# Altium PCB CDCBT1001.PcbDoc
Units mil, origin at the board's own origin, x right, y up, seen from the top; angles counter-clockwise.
Board outline 2000 x 1000 mil, 4 copper layers (Top Layer, GND2, GND3, Bottom Layer), stack 61.4 mil thick; 14 components, 7 nets, 34 pads, 29 vias.
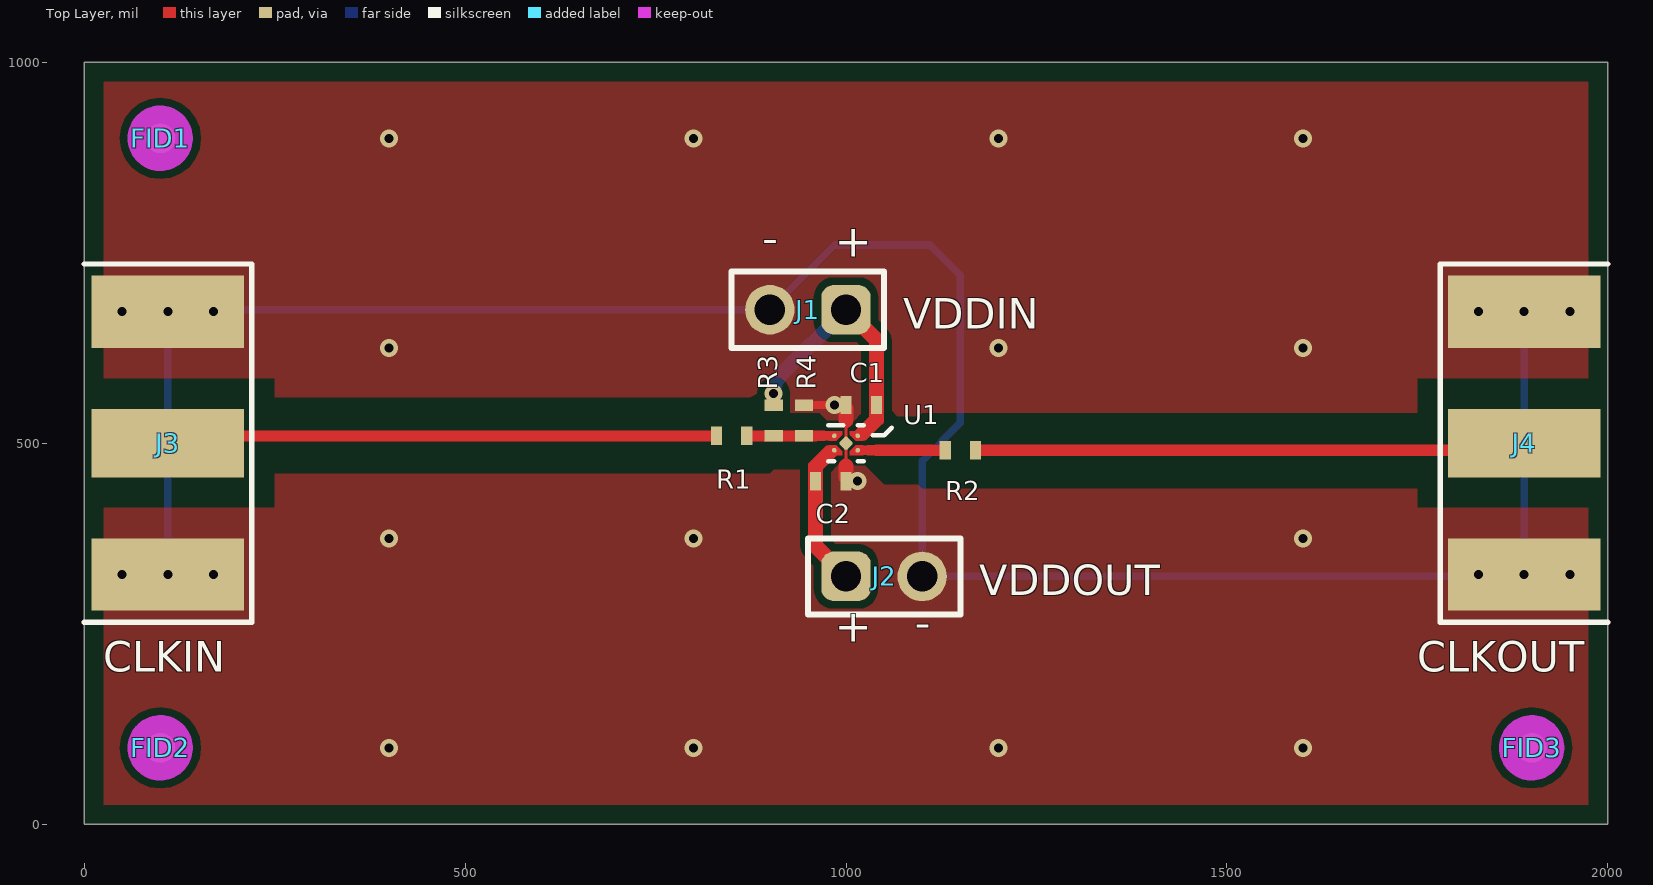
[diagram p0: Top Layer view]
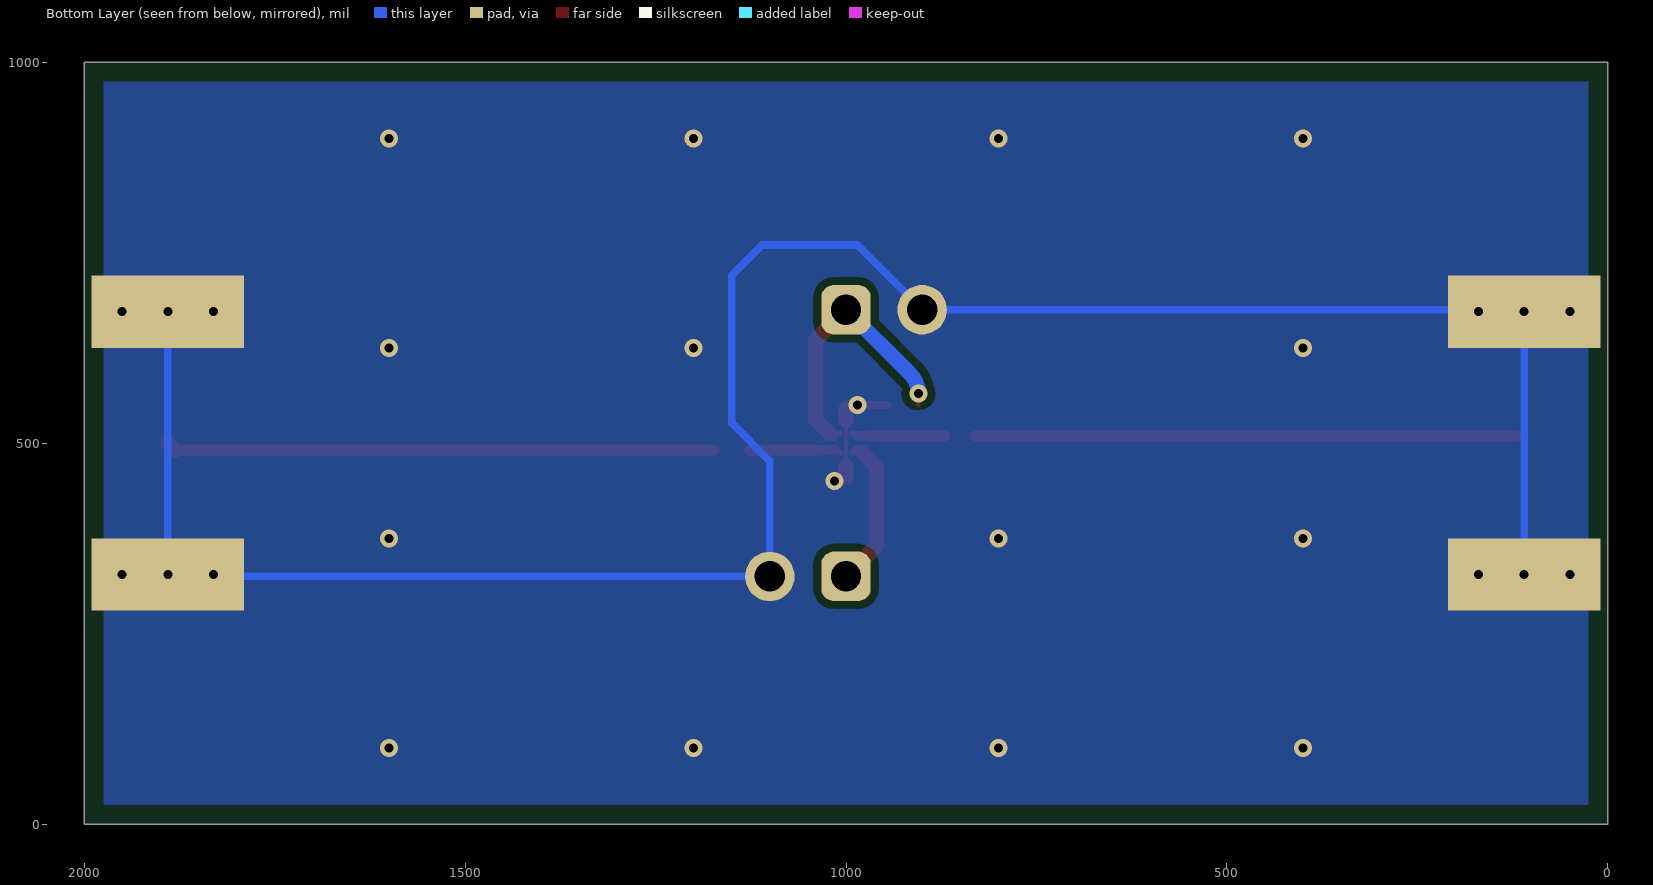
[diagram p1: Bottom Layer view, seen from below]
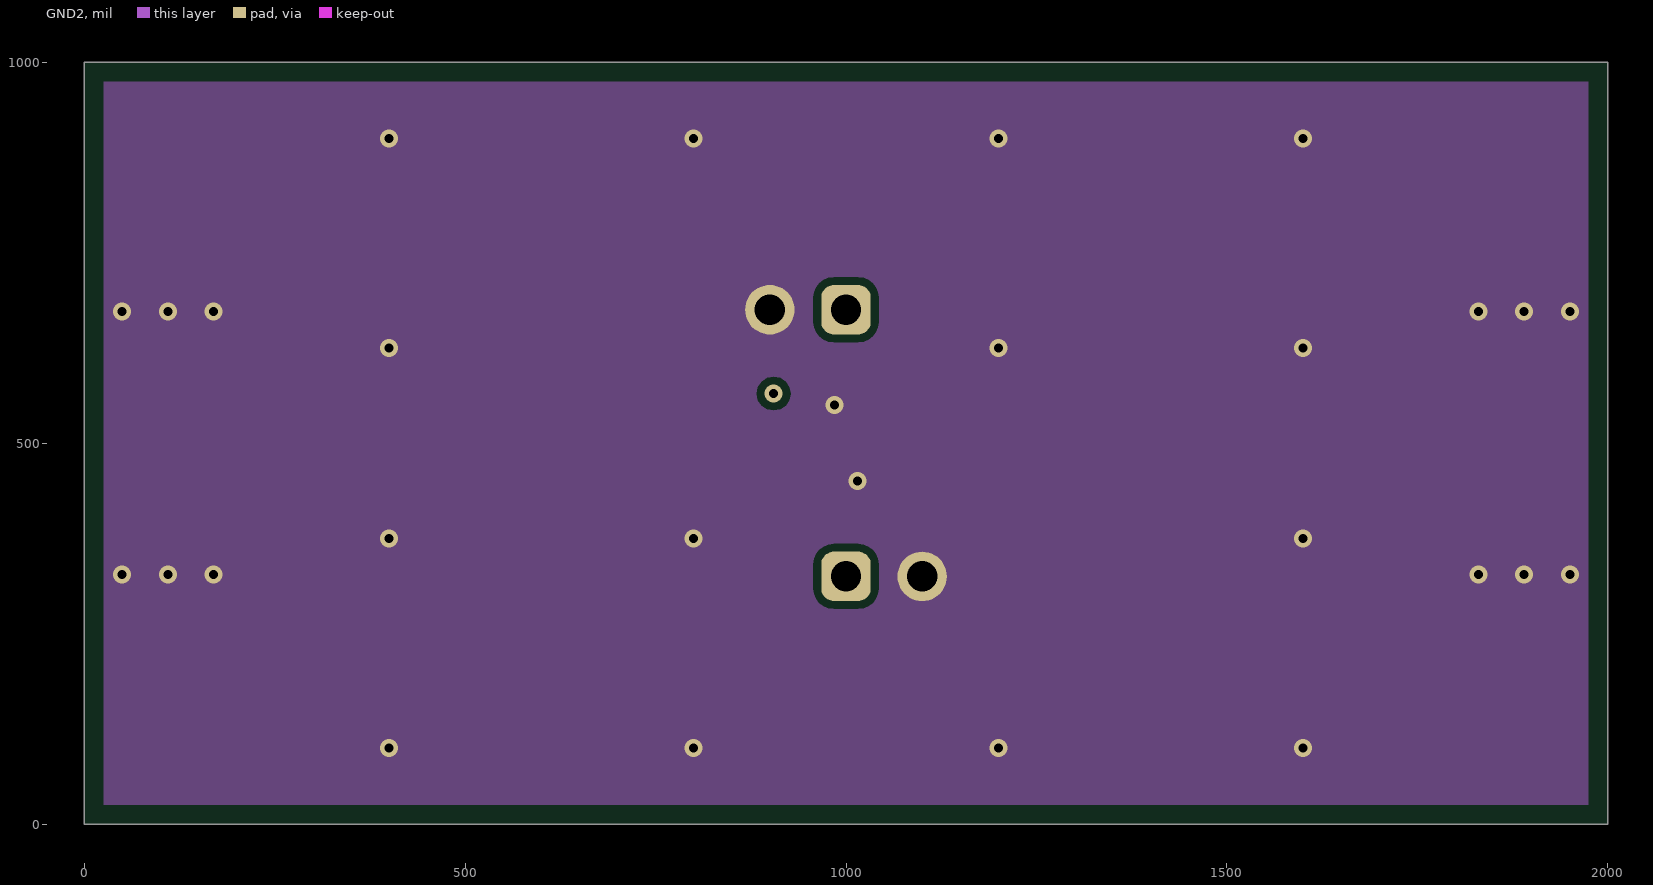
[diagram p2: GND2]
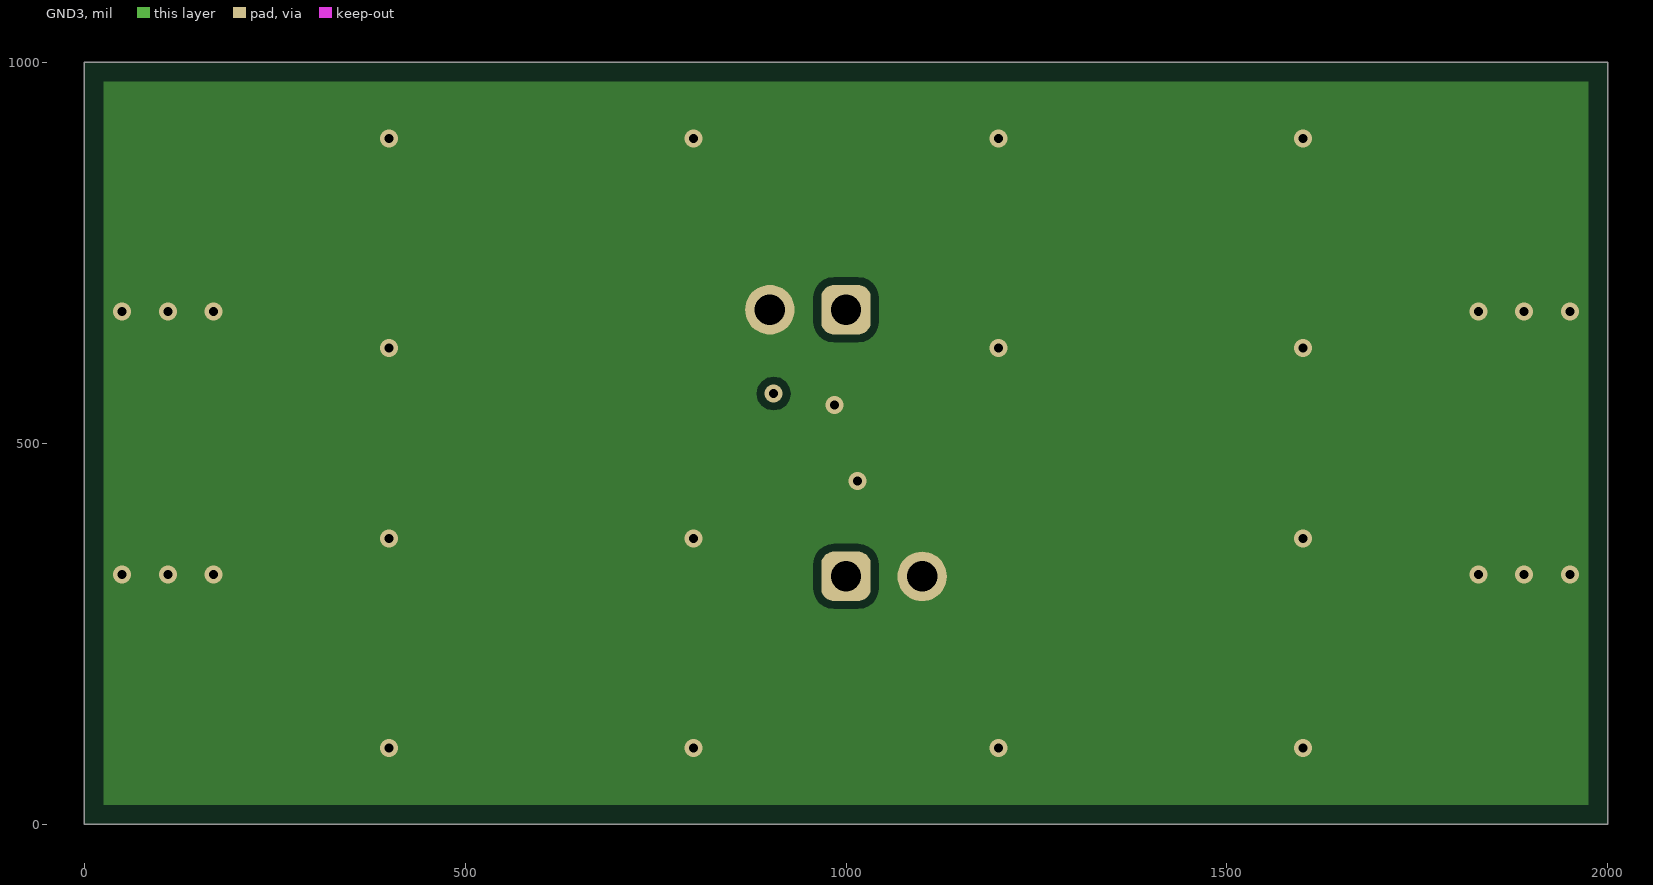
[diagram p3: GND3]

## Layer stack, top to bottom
Top Solder: solder mask 0.4, Solder Resist, Dk 3.5
Top Layer: signal copper 1.2
Dielectric 1: prepreg 8, FR-4, Dk 4.2
GND2: signal copper 1.4
Dielectric 2: core 40, FR-4, Dk 4.2
GND3: signal copper 1.4
Dielectric 3: prepreg 8, FR-4, Dk 4.2
Bottom Layer: signal copper 1.4
Bottom Solder: solder mask 0.4, Solder Resist, Dk 3.5

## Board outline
0,0 0,1000 2000,1000 2000,0

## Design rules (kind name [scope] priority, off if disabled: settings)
AcuteAngle [All] p1: minimum=4.50000000000000E+0001 checktracksonly=FALSE
AssemblyTestPointUsage [All] p1: valid=2
BoardOutlineClearance BoardOutlineClearance_MountingHoles [OnCopper and InComponentClass('Mounting Holes')] p1: gap=39.37 ignorepadtopadclearanceinfootprint=FALSE
BoardOutlineClearance BoardOutlineClearance_Poly [OnCopper and IsPoly] p2: gap=25 ignorepadtopadclearanceinfootprint=FALSE
BoardOutlineClearance [OnCopper and Not InComponentClass('Logo') and not InComponentClass('FiducialMark') and not InRegion(1000,500,4000,800) and not InPoly and not InComponent('J3') and not InComponent('J4')] p3: gap=40 ignorepadtopadclearanceinfootprint=FALSE except(25: Via-OutlineEdge Poly-OutlineEdge)
Clearance Clearance_Keepouts [((IsTrack Or IsArc) And Not InPoly) And IsFree and IsKeepOut vs ((IsTrack Or IsArc) And Not InPoly) And IsFree and IsKeepOut] p1: gap=0 ignorepadtopadclearanceinfootprint=FALSE
Clearance Clearance_Poly [InPolygon] p2: gap=10 ignorepadtopadclearanceinfootprint=TRUE
Clearance Clearance_FiducialMark [IsKeepOut and InComponentClass('FiducialMark') vs IsPad and InComponentClass('FiducialMark')] p3: gap=0 ignorepadtopadclearanceinfootprint=FALSE
Clearance [All and not InComponent('U1') and not InNet('NetR2_1') and not InNet('NetR1_2') and not InNet('NetC1_1') and not InNet('NetC2_1')and not InNet('GND')] p4: gap=7.87 ignorepadtopadclearanceinfootprint=TRUE
ComponentClearance ComponentClearance_MountingHoles_FiducialMarks [InComponentClass('Mounting Holes') vs InComponentClass('FiducialMark')] p1: gap=50 collisioncheckmode=3 verticalgap=10 showdistances=FALSE
ComponentClearance ComponentClearance_Shunt [InComponentClass('Header') vs InComponentClass('Shunt')] p2: gap=0 collisioncheckmode=3 verticalgap=0 showdistances=FALSE
ComponentClearance ComponentClearance_Logo [InComponentClass('Logo')] p3: gap=30 collisioncheckmode=3 verticalgap=10 showdistances=FALSE
ComponentClearance ComponentClearance_ScrewToNut [(HasFootprint('NY PMS 440 0025 PH')) vs (HasFootprint('Keystone_1902C'))] p4: gap=5 collisioncheckmode=3 verticalgap=10 showdistances=FALSE
ComponentClearance ComponentClearance_MountingHoles [InComponentClass('Mounting Holes')] p5: gap=100 collisioncheckmode=3 verticalgap=100000 showdistances=FALSE
ComponentClearance ComponentClearance_SmallPassives [HasFootprint('0201*') or HasFootprint('0402*') or HasFootprint('0508') or HasFootprint('0603*') or HasFootprint('0612') or HasFootprint('0805*') or HasFootprint('0815*') or HasFootprint('0830*') or HasFootprint('1206*') or HasFootprint('1210*') or HasFootprint('1808*') or HasFootprint('1812*') or HasFootprint('1825*') or HasFootprint('2010*') or HasFootprint('2220*') or HasFootprint('2225*') or HasFootprint('2512*') or HasFootprint('2728*') or HasFootprint('3518*') vs HasFootprint('0201*') or HasFootprint('0402*') or HasFootprint('0508') or HasFootprint('0603*') or HasFootprint('0612') or HasFootprint('0805*') or HasFootprint('0815*') or HasFootprint('0830*') or HasFootprint('1206*') or HasFootprint('1210*') or HasFootprint('1808*') or HasFootprint('1812*') or HasFootprint('1825*') or HasFootprint('2010*') or HasFootprint('2220*') or HasFootprint('2225*') or HasFootprint('2512*') or HasFootprint('2728*') or HasFootprint('3518*')] p6: gap=14.96 collisioncheckmode=3 verticalgap=10 showdistances=FALSE
ComponentClearance ComponentClearance_THtoSMT [IsThruComponent vs IsSMTComponent] p7: gap=30 collisioncheckmode=3 verticalgap=30 showdistances=FALSE
ComponentClearance ComponentClearance_THtoTH [IsThruComponent vs IsThruComponent] p8: gap=20 collisioncheckmode=3 verticalgap=30 showdistances=FALSE
ComponentClearance [All] p9: gap=20 collisioncheckmode=3 verticalgap=10 showdistances=FALSE
DiffPairsRouting [All] p1: maxlimit=100 minlimit=10 mostfreqgap=10 toplayer_minwidth=15 toplayer_maxwidth=15 toplayer_prefwidth=15 midlayer1_minwidth=15 midlayer1_maxwidth=15 midlayer1_prefwidth=15 midlayer2_minwidth=15 midlayer2_maxwidth=15 midlayer2_prefwidth=15 bottomlayer_minwidth=15 bottomlayer_maxwidth=15 bottomlayer_prefwidth=15 maxuncoupledlength=1000
FabricationTestPointUsage TestPointUsage [All] p1: valid=2 allowmultiple=FALSE
FabricationTestpoint Testpoint [All] p1: side=3 testpointundercomponent=TRUE minsize=40 maxsize=100 preferedsize=60 minholesize=0 maxholesize=40 preferedholesize=32 testpointgrid=1 allowsidetop=TRUE allowsidebottom=TRUE usegrid=TRUE gridtolerance=0.01
FanoutControl Fanout_LCC [IsLCC] p1: bgadir=Out bgaviamode=Centered fanoutstyle=Auto fanoutdirection=Alternating viagrid=1 // Fanout_LCC (Default Rule)
FanoutControl Fanout_BGA [IsBGA] p2: bgadir=Out bgaviamode=Centered fanoutstyle=Auto fanoutdirection=Alternating viagrid=1 // Fanout_BGA (Default Rule)
FanoutControl Fanout_Default [All] p4: bgadir=Out bgaviamode=Centered fanoutstyle=Auto fanoutdirection=Alternating viagrid=1 // Fanout_Default (Default Rule)
FanoutControl Fanout_Small [(CompPinCount < 5)] p5: bgadir=Out bgaviamode=Centered fanoutstyle=Auto fanoutdirection=OutThenIn viagrid=1 // Fanout_Small (Default Rule)
HoleSize [All] p1: absolutevalues=TRUE maxlimit=251 minlimit=3 maxpercent=80.000 minpercent=20.000
MinimumAnnularRing MinimumAnnularRing_ThermalPadVias [IsVia and InAnyComponent] p1: minimumring=3
MinimumAnnularRing [All] p2: minimumring=3.5
MinimumSolderMaskSliver MinimumSolderMaskSliver_Logo [InComponentClass('Logo') vs InComponentClass('Logo')] p1: minsoldermaskwidth=0.7
MinimumSolderMaskSliver [All] p2: minsoldermaskwidth=3.94
PlaneConnect [All] p1: planeconnectstyle=Relief reliefexpansion=10 reliefentries=4 reliefconductorwidth=10 reliefairgap=10
PolygonConnect [All] p1: connectstyle=Direct reliefconductorwidth=10 reliefentries=4 polygonreliefangle="90 Angle" airgapwidth=10
RoutingVias ThermalPadVias [IsVia and InAnyComponent] p1: holewidth=7.87 width=19.68 viastyle="Through Hole" minholewidth=3 minwidth=10 maxholewidth=12.99 maxwidth=23.62
RoutingVias [All] p2: holewidth=16 width=34 viastyle="Through Hole" minholewidth=3 minwidth=10 maxholewidth=40 maxwidth=65
SilkToBoardRegionClearance [Not ((IsComment or IsDesignator) And (Hide <> 'False')) and not InRegion(1000,500,4000,800)] p1:
SilkToSilkClearance SilkToSilkClearance_Pb-FreeLogo [(HasFootprint('Pb-Free_Overlay_Medium') OR HasFootprint('Pb-Free_Overlay_Small')) vs (HasFootprint('Pb-Free_Overlay_Medium') OR HasFootprint('Pb-Free_Overlay_Small'))] p1: silktosilkclearance=0
SilkToSilkClearance [All] p2: silktosilkclearance=3.94
SilkToSolderMaskClearance SilkToComponentPadClearance [(IsPad or IsFill or IsRegion) and InAnycomponent] p1: minsilkscreentomaskgap=5 clearancetoexposedcopper=TRUE
SilkToSolderMaskClearance "Silk to Solder Mask Opening" [All] p2: minsilkscreentomaskgap=3.94 clearancetoexposedcopper=FALSE
SolderMaskExpansion [All] p1: expansion=1.97
UnRoutedNet [All] p1: checkbadconnections=TRUE
Width [All] p1: maxlimit=100 minlimit=3.5 preferedwidth=10 checkconnectedcopper=TRUE
14 further rules are at their usual default settings.

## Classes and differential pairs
component class Header: J1 J2
component class FiducialMark: FID1 FID2 FID3

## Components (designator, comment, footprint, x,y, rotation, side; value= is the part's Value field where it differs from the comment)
C1 "885012205037" 0402S 1020,550 r180 top value=0.1µF
C2 "885012205037" 0402S 980,450 r0 top value=0.1µF
FID1 "Fiducial" Fiducial10-20 100,900 r0 top
FID2 "Fiducial" Fiducial10-20 100,100 r0 top
FID3 "Fiducial" Fiducial10-20 1900,100 r0 top
J1 "VDDIN" TSW-102-07-G-S 950,675 r180 top
J2 "VDDOUT" TSW-102-07-G-S 1050,325 r0 top
J3 "CLKIN" Emerson_142-0701-851 0,500 r90 top
J4 "CLKOUT" Emerson_142-0701-851 2000,500 r270 top
R1 "CRCW040215R0FKED" 0402S 850,509.45 r0 top value=15.0
R2 "CRCW040215R0FKED" 0402S 1150,490.55 r0 top value=15.0
R3 "CRCW0402100RFKED" 0402S 905,529.45 r90 top value=100
R4 "CRCW0402100RFKED" 0402S 945,529.45 r270 top value=100
U1 "CDCBT1001DPWR" DPW0005A-MFG 1000,500 r0 top

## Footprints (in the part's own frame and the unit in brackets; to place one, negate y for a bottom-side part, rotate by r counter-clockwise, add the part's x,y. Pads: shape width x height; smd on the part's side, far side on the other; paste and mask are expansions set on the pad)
0402S [mil] "Based on C0402S footprint from PADS legacy"
  rect 15x24 smd: 1(-20,0) 2(20,0)
  body extent -22,-12 22,12, height 24
DPW0005A-MFG [mm]
  round 0.152 smd paste-1000 mask-1000: 1(-0.39,0.24) 2(-0.39,-0.24) 4(0.39,-0.24) 5(0.39,0.24)
  rrect29% 0.35x0.35 smd rot 135 paste-1000 mask-1000: 3(0,0)
  Top Layer region: 0.65,-0.3 0.637,-0.35 0.6,-0.387 0.55,-0.4 0.55,-0.4 0.13,-0.4 0.13,-0.27 0.32,-0.08 0.55,-0.08 0.6,-0.093 0.637,-0.13 0.65,-0.18 0.65,-0.18
  Top Layer region: -0.65,-0.3 -0.637,-0.35 -0.6,-0.387 -0.55,-0.4 -0.55,-0.4 -0.13,-0.4 -0.13,-0.27 -0.32,-0.08 -0.55,-0.08 -0.6,-0.093 -0.637,-0.13 -0.65,-0.18 -0.65,-0.18
  Top Layer region: 0.65,0.3 0.637,0.35 0.6,0.387 0.55,0.4 0.55,0.4 0.13,0.4 0.13,0.27 0.32,0.08 0.55,0.08 0.6,0.093 0.637,0.13 0.65,0.18 0.65,0.18
  Top Layer region: -0.65,0.3 -0.637,0.35 -0.6,0.387 -0.55,0.4 -0.55,0.4 -0.13,0.4 -0.13,0.27 -0.32,0.08 -0.55,0.08 -0.6,0.093 -0.637,0.13 -0.65,0.18 -0.65,0.18
  silkscreen extent -0.6,-0.6 0.6,0.6, body extent -0.75,-0.53 0.75,0.53, height 0.25
Emerson_142-0701-851 [mil] "Cinch Connectivity"
  rect 90x200 smd: 1(0,-110)
  rect 95x200 smd: 2(-172.5,-110) 3(172.5,-110)
  rect 95x200 smd far side: 4(172.5,-110) 5(-172.5,-110)
  silkscreen extent -235,-220 235,0, body extent -190,-195 190,387, height 155
Fiducial10-20 [mm]
  round 1 smd mask+0.5: 1(0,0)
  Top Layer keep-out circle w1.178: c0,0 r0.5
TSW-102-07-G-S [mm] "Samtec 100mil, 1x2, 230 mil above insulator"
  rrect50% 1.65x1.65 hole 1.016: 1(-1.27,0)
  round 1.65 hole 1.016: 2(1.27,0)
  silkscreen extent -2.54,-1.27 2.54,1.27, body extent -2.54,-1.27 2.54,1.27, height 8.38

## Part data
C1 C2: library part CMP-0006228-2, "CAP, CERM, 0.1 uF, 16 V, +/- 10%, X7R, 0402", Cap_Case=0402, Manufacturer="Wurth Elektronik", Supplier Part Number 1=732-7532-1-ND, TempCo=X7R, Tolerance_%=10%, Value1=Unknown, Value2=16V, ValueDisplayed=0.1µF
FID1 FID2 FID3: library part CMP-0077181-1, "Fiducial mark.  There is nothing to buy or mount.", Manufacturer=N/A
J1 J2: library part CMP-0075405-3, "Header, 100mil, 2x1, Gold, TH", Color=Black, Current_A=6.3A, Manufacturer=Samtec, PartNumber=TSW-102-07-G-S, Supplier Part Number 1=SAM1029-02-ND, Voltage_V=550V
J3 J4: library part CMP-0055822-3, "Connector, End launch SMA, 50 ohm, SMT", Manufacturer="Cinch Connectivity", PartNumber=142-0701-851, Supplier Part Number 1=J658-ND
R1 R2: library part CMP-0026030-3, "RES, 15.0, 1%, 0.063 W, AEC-Q200 Grade 0, 0402", Manufacturer=Vishay-Dale, Power_W=63mW, Supplier Part Number 1=541-15.0LCT-ND, TempCo="100 ppm/C", Tolerance_%=1%, Value2=0.063W, Value_Code=15R0, ValueDisplayed=15.0
R3 R4: library part CMP-0025951-3, "RES, 100, 1%, 0.063 W, AEC-Q200 Grade 0, 0402", Manufacturer=Vishay-Dale, Power_W=63mW, Supplier Part Number 1=541-100LCT-ND, TempCo="100 ppm/C", Tolerance_%=1%, Value2=0.063W, Value_Code=100R, ValueDisplayed=100
U1: library part CMP-0094493-1, "1.2 to 1.8-V Clock Buffer And Level Translator", Frequency_Fixed=24MHz, Manufacturer="Texas Instruments", Operating Temperature Range="-40°C to +85°C"

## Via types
v1: diameter 23.62, hole 11.81, Top Layer to Bottom Layer, tented both sides, 29 vias

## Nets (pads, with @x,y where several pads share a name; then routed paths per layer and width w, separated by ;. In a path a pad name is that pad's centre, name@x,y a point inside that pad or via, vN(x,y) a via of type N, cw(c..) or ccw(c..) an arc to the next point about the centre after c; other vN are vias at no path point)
GND: C1.2 C2.2 J1.2 J2.2 J3.2 J3.3 J3.4 J3.5 J4.2 J4.3 J4.4 J4.5 R4.1 U1.3 | length 3174.7
  Top Layer w4: C2.2 U1.3 C1.2
  Top Layer w10: R4.1 cw(c946.33,548.12) 946.33,550 v1(985,550) C1.2
  Top Layer w20: C2.2@1000,455 1000,470 ; 1000,530 C1.2@1000,545
  Bottom Layer w10: v1(110,327.5) v1(110,672.5) 112.5,675 J1.2 985,760 1110,760 1150,720 1150,526.38 1100,476.38 J2.2 1887.5,325 v1(1890,327.5) v1(1890,672.5)
  other v1: 400,100 800,100 1200,100 1600,100 50,327.5 170,327.5 1830,327.5 1950,327.5 400,375 800,375 1600,375 1015,450 400,625 1200,625 1600,625 50,672.5 170,672.5 1830,672.5 1950,672.5 400,900 800,900 1200,900 1600,900
NetC1_1: C1.1 J1.1 R3.2 U1.5 | length 486.6
  Top Layer w5.72: 1015,506 1025,506 1047.13,528.13
  Top Layer w6: R3.2 v1(905,565) ; 1010,510 1035,535 ; U1.5 1040,534.09
  Top Layer w10: 1020,510 1040,530 ; 1045,529 C1.1@1045,555
  Top Layer w20: J1.1 1040,635 C1.1 1040,534.09
  Bottom Layer w20: v1(905,565) cw(c941.21,565) 915.61,590.61 J1.1
NetC2_1: C2.1 J2.1 U1.2 | length 322.3
  Top Layer w5.72: 952.87,471.87 975,494 985,494
  Top Layer w6: 960,465.91 U1.2 ; 965.35,465.35 990,490
  Top Layer w10: C2.1@955,445 955,471 ; 960,470 979.65,489.65
  Top Layer w20: 960,465.91 C2.1 960,365 J2.1
NetJ3_1: J3.1 R1.1 | length 723.9
  Top Layer w6: J3.1 J3.1@119.45,509.45
  Top Layer w14.6: J3.1@119.45,509.45 R1.1
NetJ4_1: J4.1 R2.2 | length 720.3
  Top Layer w14.6: R2.2@1173.62,490.55 J4.1@1880.55,490.55
  Top Layer w20: J4.1@1880.55,490.55 J4.1
NetR1_2: R1.2 R3.1 R4.2 U1.1 | length 117.7
  Top Layer w12.6: 965,509.45 U1.1@983,509.45
  Top Layer w13.6: 960,509.45 970,509.45
  Top Layer w14.6: R1.2@870,510 870.55,509.45 873.62,509.45 R3.1 ; R3.1@905.55,509.45 R4.2 960,509.45
NetR2_1: R2.1 U1.4 | length 114.4
  Top Layer w12.6: U1.4@1017,490.55 1035,490.55
  Top Layer w13.6: 1030,490.55 1040,490.55
  Top Layer w14.6: 1040,490.55 R2.1@1126.38,490.55
pads on no net: FID1.1 FID2.1 FID3.1

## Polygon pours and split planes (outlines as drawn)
GND on Top Layer "TOP_LAYER_GND_P000" (solid, pour order 0): 0,1000 2000,1000 2000,0 0,0
GND on Bottom Layer "BOTTOM_LAYER_GND_P002" (solid, remove dead copper, pour order 2): 0,1000 2000,1000 2000,0 0,0
GND on GND2 "GND2_GND_P004" (solid, remove dead copper, pour order 4): 0,1000 2000,1000 2000,0 0,0
GND on GND3 "GND3_GND_P006" (solid, remove dead copper, pour order 6): 0,1000 2000,1000 2000,0 0,0

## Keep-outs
Keep-Out Layer:
  text ".Layer_Name" at -23,-858.49 h60

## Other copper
Top Layer:
  pour cut-out: 2000,585 1750,585 1750,540 1100,540 1095,535 1050,535 1000,485 975,485 975,470 1025,470 1050,445 1095,445 1100,440 1750,440 1750,415 2000,415
  pour cut-out: 890,436.81
  pour cut-out: 0,585 250,585 250,560 900,560 920,540 965,540 975,530 1030,530 1030,515 1000,515 950,465 905,465 900,460 250,460 250,415 0,415
  text ".Layer_Name" at -23,-858.49 h60
GND2:
  text ".Layer_Name" at -3,-858.49 h60
GND3:
  text ".Layer_Name" at -23,-858.49 h60
Bottom Layer:
  text ".Layer_Name" at -23,-858.49 h60

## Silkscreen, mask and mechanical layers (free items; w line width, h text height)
Top Overlay:
  lines w6: 1035,510 1050,510 1060,520
  text "-" at 890,735 h72.83
  text "+" at 985,730 h72.83
  text "-" at 1090,230 h72.83
  text "+" at 985,225 h72.83
  text ".Layer_Name" at -23,-858.49 h60
Bottom Overlay:
  text ".Layer_Name" at -23,-858.49 h60
Top Paste:
  text ".Layer_Name" at -23,-858.49 h60
Bottom Paste:
  text ".Layer_Name" at -23,-858.49 h60
Top Solder:
  text ".Layer_Name" at -23,-858.49 h60
  text ".Layer_Name" at -23,-858.49 h60
Bottom Solder:
  text ".Layer_Name" at -23,-858.49 h60
Drill Guide:
  text ".Layer_Name" at -23,-858.49 h60
M1 Board Outline:
  the board outline again, w10
  text ".Layer_Name" at -23,-858.49 h60
M2 Board Dimensions:
  rectangle: -600,-275 -475,-150
  rectangle: -475,-400 -100,-275
  lines w7: -600,-275 400,-275 ; -475,-400 -475,-150 ; -350,-400 -350,-150 ; -100,-400 -100,-150 ; 150,-400 150,-150 ; -600,-400 400,-400 400,-150 -600,-150 -600,-400
  text ".Layer_Name" at -23,-858.49 h60
M3 3D STEP Top:
  text ".Layer_Name" at -23,-858.49 h60
M4 3D STEP Bottom:
  text ".Layer_Name" at -23,-858.49 h60
M5 Assembly Top:
  lines w10: -892,-930.17 5708,-930.17 ; -892,-726.83 5710,-726.83 ; -892,-523.5 -892,-1133.5 3113,-1133.5 5710,-1133.5 5710,-523.5 -891.5,-523.5 -891.5,-1133.5 684,-1133.5 ; 1573,-1133.5 1573,-523.5 ; 2840,-726.83 2840,-523.5 ; 3680,-726.83 3680,-523.5 ; 4302,-1140 4302,-937.17
  text "COMPONENTS MARKED 'DNP' SHOULD NOT BE POPULATED." at 553.5,-318.5 h60
  text "ASSEMBLY VARIANT:" at 553,-434 h60
  text ".VariantName" at 1589,-434 h60
  text "PCB VIEWED FROM TOP SIDE" at -828.5,-655.67 h60
  text "BOARD #:" at 1648,-655.67 h60
  text ".PRJ_Number" at 2193.5,-655.67 h60
  text "REV:" at 3038,-655.67 h60
  text ".PCB_Rev" at 3329.5,-655.67 h60
  text "SVN REV:" at 3876,-655.67 h60
  text ".VersionControl_RevNumber" at 4382,-655.67 h60
  text "TID #:" at 1648,-859 h60
  text ".TID" at 2193.5,-859 h60
  text "PLOT NAME =" at -828.5,-1064.34 h60
  text ".plot_File_Name" at -23,-1064.34 h60
  text "GENERATED    :" at 1650,-1064.34 h60
  text ".Print_Date" at 2519.5,-1064.34 h60
  text ".Print_Time" at 3248.5,-1064.34 h60
M6 Assembly Bottom:
  lines w10: -892.5,-727.33 5709.5,-727.33 ; -890.5,-930.67 5709.5,-930.67 ; 515.5,-1140.5 515.5,-937.67 ; 1137.5,-727.33 1137.5,-524 ; 1977.5,-727.33 1977.5,-524 ; 3244.5,-1134 3244.5,-524 ; 4133.5,-1134 5709,-1134 5709,-524 -892.5,-524 -892.5,-1134 1704.5,-1134 5709.5,-1134 5709.5,-524
  text "COMPONENTS MARKED 'DNP' SHOULD NOT BE POPULATED." at 5502,-318 h60
  text ".VariantName" at 4458,-434 h60
  text "ASSEMBLY VARIANT:" at 5497,-434 h60
  text ".VersionControl_RevNumber" at 435.5,-656.17 h60
  text "SVN REV:" at 941.5,-656.17 h60
  text ".PCB_Rev" at 1488,-656.17 h60
  text "REV:" at 1779.5,-656.17 h60
  text ".PRJ_Number" at 2624,-656.17 h60
  text "BOARD #:" at 3169.5,-656.17 h60
  text "PCB VIEWED FROM BOTTOM SIDE" at 5646,-656.17 h60
  text ".TID" at 2624,-859.5 h60
  text "TID #:" at 3169.5,-859.5 h60
  text ".Print_Time" at 1569,-1064.84 h60
  text ".Print_Date" at 2298,-1064.84 h60
  text "GENERATED    :" at 3167.5,-1064.84 h60
  text ".plot_File_Name" at 4840.5,-1064.84 h60
  text "PLOT NAME =" at 5646,-1064.84 h60
M9 Title Sheet:
  lines w10: -1091.5,1041.5 -891.5,1041.5 ; -1091.5,3416.5 -891.5,3416.5 ; -1091.5,5791.5 -891.5,5791.5 ; 1408.5,-1333.5 1408.5,-1133.5 ; 1408.5,7966.5 1408.5,8166.5 ; 3908.5,-1333.5 3908.5,-1133.5 ; 3908.5,7966.5 3908.5,8166.5 ; 5721,-1133.5 5721,-523.5 10703.5,-523.5 ; 6408.5,-1333.5 6408.5,-1133.5 ; 6408.5,7966.5 6408.5,8166.5 ; 8908.5,-1333.5 8908.5,-1133.5 ; 8908.5,7966.5 8908.5,8166.5 ; 10703.5,-1133.5 10703.5,-523.5 ; 10703.5,-823.5 13703.5,-823.5 ; 10703.5,-223.5 13703.5,-223.5 ; 10704.5,370.5 13704.5,370.5 ; 11408.5,-1333.5 11408.5,-1133.5 ; 11408.5,7966.5 11408.5,8166.5 ; 12208.5,-1123.5 12208.5,-523.5 ; 13703.5,-523.5 10703.5,-523.5 ; 13703.5,76.5 10703.5,76.5 ; 13708.5,66.5 13708.5,-1133.5 ; 13708.5,871 10704.5,871 10703.5,871 10703.5,370.5 10703.5,76.5 ; 13708.5,1041.5 13908.5,1041.5 ; 13708.5,3416.5 13908.5,3416.5 ; 13708.5,5791.5 13908.5,5791.5 ; 10703.5,-523.5 10703.5,76.5 ; 13708.5,-1133.5 13708.5,7966.5 -891.5,7966.5 -891.5,-1133.5 13708.5,-1133.5 ; -1091.5,-1333.5 -1091.5,8166.5 13908.5,8166.5 13908.5,-1333.5 -1091.5,-1333.5
  text "1" at 139.84,8036.5 h70
  text "2" at 2635.5,8036.5 h70
  text "3" at 5124.84,8036.5 h70
  text "4" at 7631.51,8036.5 h70
  text "5" at 10130.5,8036.5 h70
  text "6" at 12635.5,8036.5 h70
  text "A" at -1016.5,6893.5 h70
  text "A" at 13783.5,6893.5 h70
  text "B" at -1016.5,4513.5 h70
  text "B" at 13783.5,4513.5 h70
  text "C" at -1016.5,2138.5 h70
  text "C" at 13783.5,2138.5 h70
  text "PROJECT TITLE:" at 10743.5,277.5 h45
  text "DESIGNED FOR:" at 10743.5,-23.5 h45
  text ".PRJ_Customer" at 10793.5,-163.5 h70
  text "D" at -1016.5,-231.5 h70
  text "D" at 13783.5,-231.5 h70
  text "FILE NAME:" at 10743.5,-323.5 h45
  text "Texas Instruments (TI) and/or its licensors do not warrant the accuracy or completeness of this specification" at 5774,-605.34 h45
  text "ENGINEER:" at 10743.5,-613.5 h45
  text "LAYOUT BY:" at 12248.5,-613.5 h45
  text "or any information contained therein. TI and/or its licensors do not warrant that this design will meet" at 5729.01,-718 h45
  text "the specifications, will be suitable for your application or fit for any particular purpose, or will operate in" at 5729.01,-830.67 h45
  text ".Layer_Name" at -23,-858.49 h60
  text "ALTIUM DESIGNER VERSION:" at 12248.5,-923.5 h45
  text "an implementation. TI and/or its licensors do not warrant that the design is production worthy. You should" at 5729.01,-943.33 h45
  text "completely validate and test your design implementation to confirm the system functionality for your application." at 5774,-1056 h45
  text ".print_Scale" at 10793.5,-1056.83 h70
  text ".Application_BuildNumber" at 12299,-1056.83 h70
  text "1" at 139.84,-1263.5 h70
  text "2" at 2635.5,-1263.5 h70
  text "3" at 5124.84,-1263.5 h70
  text "4" at 7631.51,-1263.5 h70
  text "5" at 10130.5,-1263.5 h70
  text "6" at 12635.5,-1263.5 h70
M10 Fab Notes:
  text ".Layer_Name" at -23,-858.49 h60
M11 Gerber Information:
  lines w10: -892,-930.17 5708,-930.17 ; -892,-726.83 5710,-726.83 ; -892,-523.5 -892,-1133.5 3113,-1133.5 5710,-1133.5 5710,-523.5 -891.5,-523.5 -891.5,-1133.5 684,-1133.5 ; 1573,-1133.5 1573,-523.5 ; 2840,-726.83 2840,-523.5 ; 3680,-726.83 3680,-523.5 ; 4302,-1140 4302,-937.17
  text "ALL ARTWORK VIEWED FROM TOP SIDE" at -828.5,-655.67 h60
  text "BOARD #:" at 1648,-655.67 h60
  text ".PRJ_Number" at 2193.5,-655.67 h60
  text "REV:" at 3038,-655.67 h60
  text ".PCB_Rev" at 3329.5,-655.67 h60
  text "SVN REV:" at 3876,-655.67 h60
  text ".VersionControl_RevNumber" at 4382,-655.67 h60
  text "LAYER NAME =" at -828.5,-858.49 h60
  text "TID #:" at 1648,-859 h60
  text ".TID" at 2193.5,-859 h60
  text "PLOT NAME =" at -828.5,-1064.34 h60
  text ".plot_File_Name" at -23,-1064.34 h60
  text "GENERATED    :" at 1650,-1064.34 h60
  text ".Print_Date" at 2519.5,-1064.34 h60
  text ".Print_Time" at 3248.5,-1064.34 h60
M12 Stackup:
  drawing of 295 lines, arcs and shapes, not listed
  text "Layer" at 2567.5,1135 h60
  text "Name" at 2977.41,1135 h60
  text "Material" at 3907.16,1135 h60
  text "Thickness" at 4766.92,1135 h60
  text "Constant" at 5416.76,1135 h60
  text "Board Layer Stack" at 5986.62,1135 h60
  text "1" at 2567.5,1015 h60
  text "Top Overlay" at 2977.41,1015 h60
  text "2" at 2567.5,895 h60
  text "Top Solder" at 2977.41,895 h60
  text "Solder Resist" at 3907.16,895 h60
  text "0.40mil" at 4766.92,895 h60
  text "3.5" at 5416.76,895 h60
  text "3" at 2567.5,775 h60
  text "Top Layer" at 2977.41,775 h60
  text "Copper" at 3907.16,775 h60
  text "1.20mil" at 4766.92,775 h60
  text "4" at 2567.5,655 h60
  text "Dielectric 1" at 2977.41,655 h60
  text "FR-4" at 3907.16,655 h60
  text "8.00mil" at 4766.92,655 h60
  text "4.2" at 5416.76,655 h60
  text "5" at 2567.5,535 h60
  text "GND2" at 2977.41,535 h60
  text "Copper" at 3907.16,535 h60
  text "1.40mil" at 4766.92,535 h60
  text "6" at 2567.5,415 h60
  text "Dielectric 2" at 2977.41,415 h60
  text "FR-4" at 3907.16,415 h60
  text "40.00mil" at 4766.92,415 h60
  text "4.2" at 5416.76,415 h60
  text "7" at 2567.5,295 h60
  text "GND3" at 2977.41,295 h60
  text "Copper" at 3907.16,295 h60
  text "1.40mil" at 4766.92,295 h60
  text "8" at 2567.5,175 h60
  text "Dielectric 3" at 2977.41,175 h60
  text "FR-4" at 3907.16,175 h60
  text "8.00mil" at 4766.92,175 h60
  text "4.2" at 5416.76,175 h60
  text "9" at 2567.5,55 h60
  text "Bottom Layer" at 2977.41,55 h60
  text "Copper" at 3907.16,55 h60
  text "1.40mil" at 4766.92,55 h60
  text "10" at 2567.5,-65 h60
  text "Bottom Solder" at 2977.41,-65 h60
  text "Solder Resist" at 3907.16,-65 h60
  text "0.40mil" at 4766.92,-65 h60
  text "3.5" at 5416.76,-65 h60
  text "11" at 2567.5,-185 h60
  text "Bottom Overlay" at 2977.41,-185 h60
  text ".Layer_Name" at -23,-858.49 h60
M13 Component Bodies Top:
  text ".Layer_Name" at -23,-858.49 h60
M14 Component Bodies Bottom:
  text ".Layer_Name" at -23,-858.49 h60
M15 Courtyards Top:
  text ".Layer_Name" at -23,-858.49 h60
M16 Courtyards Bottom:
  text ".Layer_Name" at -23,-858.49 h60
Drill Drawing:
  lines w10: 2556.09,1676.34 2611.34,1676.34 2611.34,1731.59 2556.09,1731.59 2556.09,1676.34 ; 2556.09,1855.91 2611.34,1855.91 2583.72,1800.66 2556.09,1855.91
  lines w12: 2506,1639.04 5737.49,1639.04 ; 2506,1887.68 5737.49,1887.68 ; 2843.86,1514.72 2843.86,2012 ; 3175.86,1514.72 3175.86,2012 ; 3812.43,1514.72 3812.43,2012 ; 4071.57,1514.72 4071.57,2012 ; 4446.72,1514.72 4446.72,2012 ; 5171.05,1514.72 5171.05,2012 ; 2506,1514.72 5737.49,1514.72 5737.49,2012 2506,2012 2506,1514.72
  text "Symbol" at 2580.59,1924.98 h72
  text "Quantity" at 2881.16,1924.98 h72
  text "Finished Hole Size" at 3213.16,1924.98 h72
  text "Plated" at 3849.72,1924.98 h72
  text "Hole Type" at 4108.86,1924.98 h72
  text "Drill Layer Pair" at 4484.02,1924.98 h72
  text "Hole Tolerance" at 5208.35,1924.98 h72
  text "29" at 2881.16,1800.66 h60
  text "11.81mil (0.300mm)" at 3213.16,1800.66 h60
  text "PTH" at 3849.72,1800.66 h60
  text "Round" at 4108.86,1800.66 h60
  text "Top Layer - Bottom Layer" at 4484.02,1800.66 h60
  text "4" at 2881.16,1676.34 h60
  text "40.00mil (1.016mm)" at 3213.16,1676.34 h60
  text "PTH" at 3849.72,1676.34 h60
  text "Round" at 4108.86,1676.34 h60
  text "Top Layer - Bottom Layer" at 4484.02,1676.34 h60
  text "33 Total" at 2881.16,1552.02 h60
  text ".Layer_Name" at -23,-858.49 h60
Mechanical 17:
  text ".Layer_Name" at -23,-858.49 h60
Mechanical 18:
  text ".Layer_Name" at -23,-858.49 h60
Mechanical 19:
  text ".Layer_Name" at -23,-858.49 h60

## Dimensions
-600,-400 to 400,-400 on M2 Board Dimensions
-100,0 to -100,1000 on M2 Board Dimensions
2000,1100 to 0,1100 on M2 Board Dimensions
